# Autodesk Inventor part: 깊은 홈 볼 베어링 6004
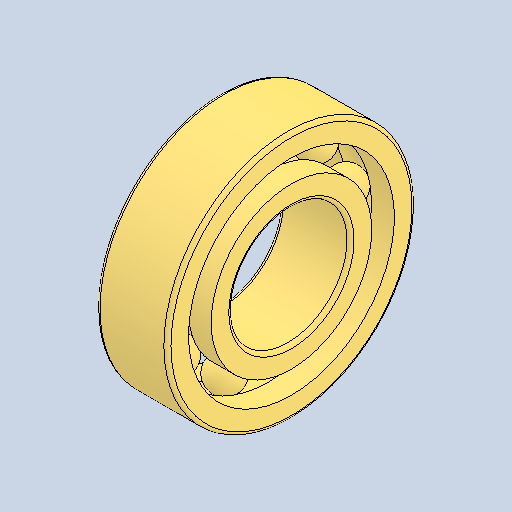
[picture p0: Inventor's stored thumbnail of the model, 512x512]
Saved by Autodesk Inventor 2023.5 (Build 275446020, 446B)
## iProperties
Created: 2026-07
Part Number: 깊은 홈 볼 베어링 6004
Material: 강철, 연강
Description: 깊은 그루브 볼 베어링
Document SubType Name: Modeling
Designer: 1강의실14
Density: 7.85 g/cm^3
Appearance: 기본값
Author: jhkim
Sending System: Autodesk Inventor 2027
Preprocessor: ST-DEVELOPER v20.1
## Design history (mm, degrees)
node "깊은 홈 볼 베어링 60041"
node "솔리드1"
node "솔리드2"
node "솔리드3"
node "솔리드4"
node "솔리드5"
node "솔리드6"
node "솔리드7"
node "솔리드8"
node "솔리드9"
node "솔리드10"
node "솔리드11"
body "Solid1"
node "Solid1:1"
node "Solid1:2"
node "Solid1:3"
node "Solid1:4"
node "Solid1:5"
node "Solid1:6"
node "Solid1:7"
node "Solid1:8"
node "Solid1:9"
node "Solid1:10"
